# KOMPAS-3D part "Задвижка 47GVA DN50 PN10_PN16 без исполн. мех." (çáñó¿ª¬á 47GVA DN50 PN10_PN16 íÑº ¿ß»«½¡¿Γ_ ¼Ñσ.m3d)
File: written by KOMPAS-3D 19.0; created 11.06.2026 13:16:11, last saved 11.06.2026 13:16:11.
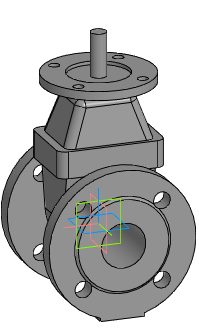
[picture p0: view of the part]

Document properties: Автор: Евгений; Полное имя файла: Z:\3.Личные\kachalov\001_3d для проектировщиков\2.2 Тип 47GVA, 47GVA.Z\_stp\_stp_Задвижка 47GVA DN40-DN1000 без исп.мех\Задвижка 47GVA DN50 PN10_PN16 без исполнит_ мех.m3d

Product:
- Part/product: Задвижка 47GVA DN50 PN10_PN16 без исполн. мех.

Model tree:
1. Операция без истории:1  (labels: Задвижка 47GVA DN50 PN10_PN16 без исполн. мех.)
